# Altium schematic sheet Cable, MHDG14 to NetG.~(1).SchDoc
size B
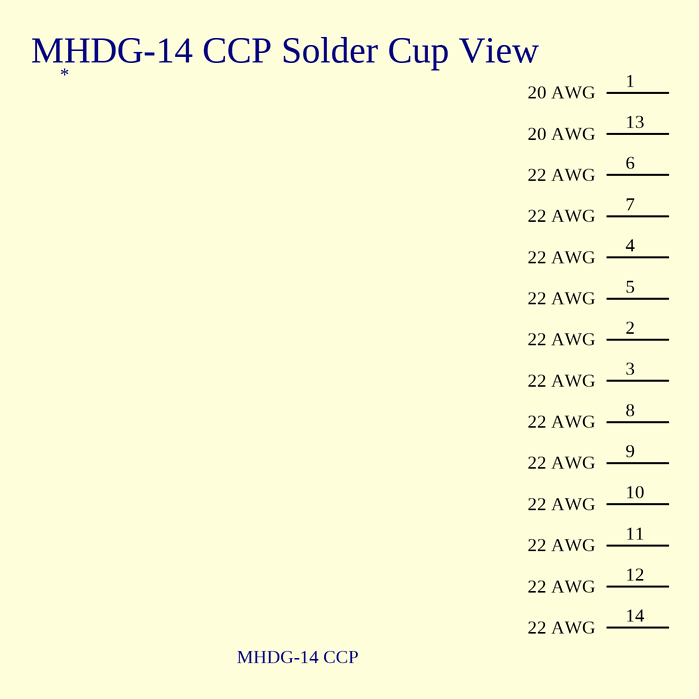
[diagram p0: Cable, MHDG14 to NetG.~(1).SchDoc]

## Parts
*  MHDG-14 CCP

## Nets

Not connected (* = marked no-connect by the designer): * 1(20_AWG) 2(22_AWG) 3(22_AWG) 4(22_AWG) 5(22_AWG) 6(22_AWG) 7(22_AWG) 8(22_AWG) 9(22_AWG) 10(22_AWG) 11(22_AWG) 12(22_AWG) 13(20_AWG) 14(22_AWG)

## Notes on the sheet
- (near *) MHDG-14 CCP Solder Cup View

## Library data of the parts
* = MHDG-14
